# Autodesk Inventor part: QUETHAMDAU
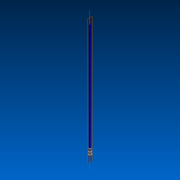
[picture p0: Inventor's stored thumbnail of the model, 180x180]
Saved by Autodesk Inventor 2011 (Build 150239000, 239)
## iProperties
Created: 2011-04
Part Number: QUETHAMDAU
Document SubType Name: Modeling
Designer: TRINH
Density: 1 g/cm^3
Author: TRINH
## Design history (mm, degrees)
sketch "Sketch1"
  geometry: C1 r 9 at (0, 0); 1 further point
  constraints: 1 centre point, 1 coincident
  dimensions: "d0" = 18 diameter of C1
extrude "Extrusion1" new body sketch "Sketch1" distance "d1" = 6; taper "d2" = 0 deg
sketch "Sketch2"
  geometry: C1 r 9 at (0, 0) reference; C2 r 6 at (0, 0)
  constraints: 1 centre point, 1 coincident
  dimensions: "d3" = 12 diameter of C2
extrude "Extrusion2" join sketch "Sketch2" distance "d4" = 9; taper "d5" = 0 deg
sketch "Sketch3"
  geometry: C1 r 6 at (0, 0) reference; C2 r 8 at (0, 0)
  constraints: 1 centre point, 1 coincident
  dimensions: "d6" = 16 diameter of C2
extrude "Extrusion3" join sketch "Sketch3" distance "d7" = 4; taper "d8" = 0 deg
sketch "Sketch4"
  geometry: C1 r 8 at (0, 0) reference; C2 r 5 at (0, 0)
  constraints: 1 centre point, 1 coincident
  dimensions: "d9" = 10 diameter of C2
extrude "Extrusion4" join sketch "Sketch4" distance "d10" = 2; taper "d11" = 0 deg
sketch "Sketch5"
  geometry: C1 r 5 at (0, 0) reference; C2 r 6 at (0, 0)
  constraints: 1 centre point, 1 coincident
  dimensions: "d12" = 12 diameter of C2
extrude "Extrusion5" join sketch "Sketch5" distance "d13" = 9; taper "d14" = 0 deg
sketch "Sketch6"
  geometry: C1 r 6 at (0, 0) reference; C2 r 3 at (0, 0)
  constraints: 1 centre point, 1 coincident
  dimensions: "d15" = 6 diameter of C2
extrude "Extrusion6" join sketch "Sketch6" distance "d16" = 515; taper "d17" = 0 deg
chamfer "Chamfer1" distance "d18" = 1; stored, may be unused: second distance "d19" = 2, angle "d20" = 45 deg
chamfer "Chamfer2" distance "d21" = 0.5; stored, may be unused: second distance "d22" = 2, angle "d23" = 45 deg
fillet "Fillet1" dims "d24" = 1
thread "Thread1" dims "d25" = 10, "d26" = 0
fillet "Fillet2" dims "d27" = 1
sketch "Sketch7"
  geometry: C1 r 8.5 at (0, 0) reference; C2 r 2.5 at (0, 0)
  constraints: 1 centre point, 1 coincident
  dimensions: "d28" = 5 diameter of C2
extrude "Extrusion7" join sketch "Sketch7" distance "d29" = 2.5; taper "d30" = 0 deg
fillet "Fillet3" dims "d31" = 2.5
workplane "Work Plane1"
  workaxis "Work Axis1"
body "Solid1"
other parameters: "d32" = 90 deg
